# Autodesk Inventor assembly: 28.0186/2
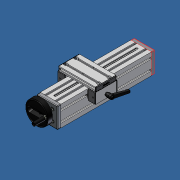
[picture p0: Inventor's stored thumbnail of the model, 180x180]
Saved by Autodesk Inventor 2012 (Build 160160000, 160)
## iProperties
Created: 2007-06
Part Number: 28.0186/2
Document SubType Name: Assembly
Designer: Andy Moles
Description: ADJUSTING UNIT VEN 90 WITH SIDE CLAMP
Author: Andy Moles
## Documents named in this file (23)
- C:\Andys Backup Data\ANDY'S INVENTOR\INVENTOR LIBRARIES\PARTS LIBRARY\READY FOR USE MODULES LG\28.0186_2 ADJUSTING UNIT VEN 90 WITH SIDE CLAMP.iam
- C:\Andys Backup Data\ANDY'S INVENTOR\INVENTOR LIBRARIES\PARTS LIBRARY\READY FOR USE MODULES LG\SUBCOMPONENTS\28.0216_1 90x90S.ipt
- C:\Andys Backup Data\ANDY'S INVENTOR\INVENTOR LIBRARIES\PARTS LIBRARY\READY FOR USE MODULES LG\SUBCOMPONENTS\50.1264 BALL BEARING 10X30X9 6200 2RS DIN 625.ipt
- C:\Andys Backup Data\ANDY'S INVENTOR\INVENTOR LIBRARIES\PARTS LIBRARY\READY FOR USE MODULES LG\SUBCOMPONENTS\28.0205 BEARING PLATE 90X90 HANDWHEEL SIDE.ipt
- C:\Andys Backup Data\ANDY'S INVENTOR\INVENTOR LIBRARIES\PARTS LIBRARY\READY FOR USE MODULES LG\SUBCOMPONENTS\28.0206 BEARING PLATE 90X90 IDLER SIDE.ipt
- C:\Andys Backup Data\ANDY'S INVENTOR\INVENTOR LIBRARIES\PARTS LIBRARY\READY FOR USE MODULES LG\SUBCOMPONENTS\28.0204 HANDWHEEL 100mm.iam
- C:\Andys Backup Data\ANDY'S INVENTOR\INVENTOR LIBRARIES\PARTS LIBRARY\READY FOR USE MODULES LG\SUBCOMPONENTS\28.0221 ACME SCREW 16X4.ipt
- C:\Andys Backup Data\ANDY'S INVENTOR\INVENTOR LIBRARIES\PARTS LIBRARY\FASTENING ELEMENTS\WASHERS\21.1326 DISC SPRING 20.ipt
- C:\Andys Backup Data\ANDY'S INVENTOR\INVENTOR LIBRARIES\PARTS LIBRARY\FASTENING ELEMENTS\SCREWS CAP\21.1204 M8X25.ipt
- C:\Andys Backup Data\ANDY'S INVENTOR\INVENTOR LIBRARIES\PARTS LIBRARY\READY FOR USE MODULES LG\SUBCOMPONENTS\28.0255 Nut slide connector 20.ipt
- C:\Andys Backup Data\ANDY'S INVENTOR\INVENTOR LIBRARIES\PARTS LIBRARY\READY FOR USE MODULES LG\SUBCOMPONENTS\28.0224_1 LWN 32X45-90 90X19-NSC.ipt
- C:\Andys Backup Data\ANDY'S INVENTOR\INVENTOR LIBRARIES\PARTS LIBRARY\READY FOR USE MODULES LG\SUBCOMPONENTS\28.0257 BRONZE NUT 16X4 NOTCHED.ipt
- C:\Andys Backup Data\ANDY'S INVENTOR\INVENTOR LIBRARIES\PARTS LIBRARY\FASTENING ELEMENTS\SCREWS CAP\21.1235 M5X16.ipt
- C:\Andys Backup Data\ANDY'S INVENTOR\INVENTOR LIBRARIES\PARTS LIBRARY\FASTENING ELEMENTS\SCREWS CAP\21.1200 M8X16.ipt
- C:\Andys Backup Data\ANDY'S INVENTOR\INVENTOR LIBRARIES\PARTS LIBRARY\READY FOR USE MODULES LG\SUBCOMPONENTS\28.0126 SLIDE 45X32.ipt
- C:\Andys Backup Data\ANDY'S INVENTOR\INVENTOR LIBRARIES\PARTS LIBRARY\READY FOR USE MODULES LG\SUBCOMPONENTS\28.0126_9 SIDE LOCK 45X32.ipt
- C:\Andys Backup Data\ANDY'S INVENTOR\INVENTOR LIBRARIES\PARTS LIBRARY\COMPONENTS LG\22.1095 SLIDE RAIL LN.iam
- C:\Andys Backup Data\ANDY'S INVENTOR\INVENTOR LIBRARIES\PARTS LIBRARY\COMPONENTS LG\22.1095_9 SLIDE RAIL LN FOR SIDE LOCK.iam
- C:\Andys Backup Data\ANDY'S INVENTOR\INVENTOR LIBRARIES\PARTS LIBRARY\END CAPS\22.1003_1 END CAP 45x32 Z Gray.iam
- C:\Andys Backup Data\ANDY'S INVENTOR\INVENTOR LIBRARIES\PARTS LIBRARY\FASTENING ELEMENTS\NUTS\21.1330 M6 SQUARE NUT.ipt
- C:\Andys Backup Data\ANDY'S INVENTOR\INVENTOR LIBRARIES\PARTS LIBRARY\END CAPS\22.1014_1 END CAP 90X19 GRAY.ipt
- C:\Andys Backup Data\ANDY'S INVENTOR\INVENTOR LIBRARIES\PARTS LIBRARY\FASTENING ELEMENTS\NUTS\21.1351 M8 SQUARE NUT.ipt
- C:\Andys Backup Data\ANDY'S INVENTOR\INVENTOR LIBRARIES\PARTS LIBRARY\COMPONENTS LG\21.1013_1 SLIDE LOCK WITH M6X50 STUD.ipt
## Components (42 placed, 22 different names)
1. 28.0216_1 90x90S:1 — Flush:1, Flush:2, Flush:3, Mate:3, Flush:10, Flush:11, Mate:10, Flush:12, Flush:13, Angle:8, Mate:26, Mate:32
2. 50.1264 10X30X9 6200 2RS DIN 625 BALL BEARING:1 — Insert:7
3. 50.1264 10X30X9 6200 2RS DIN 625 BALL BEARING:2 — Insert:6, Insert:18
4. 28.0205 BEARING PLATE 90X90 HANDWHEEL SIDE:1 — Mate:3, Insert:4, Insert:7, Flush:11, Insert:8, Insert:9, Insert:10, Insert:11, Flush:13
5. 28.0206 BEARING PLATE 90X90 IDLER SIDE:1 — Insert:6, Flush:10, Insert:12, Insert:13, Insert:14, Insert:15, Mate:10, Flush:12
6. 28.0204 HANDWHEEL 100mm:1 [sub-assembly] — Insert:4, Angle:1
7. 21.1204  M8 x 25:1 — Insert:8
8. 21.1204  M8 x 25:2 — Insert:9
9. 21.1204  M8 x 25:3 — Insert:11
10. 21.1204  M8 x 25:4 — Insert:10
11. 21.1204  M8 x 25:5 — Insert:14
12. 21.1204  M8 x 25:6 — Insert:13
13. 21.1204  M8 x 25:7 — Insert:15
14. 21.1204  M8 x 25:8 — Insert:12
15. 28.0221 ACME SCREW 16X4:1 — Insert:16, Insert:17, Angle:1, Mate:20
16. 21.1326 DISC SPRING 20:1 — Insert:16
17. 21.1326 DISC SPRING 20:2 — Insert:17, Insert:18
18. 28.0255 Nut slide connector 20:1 — Insert:19, Angle:2, Mate:27
19. 28.0224_1 LWN 32X45-90 90X19-NSC:1 — Insert:19, Angle:2, Insert:20, Insert:21, Insert:22, Insert:23, Insert:24, Mate:12, Flush:14, Angle:8, Mate:28, Flush:17, Mate:35, Angle:16, Flush:19, Flush:20, Mate:36, Flush:21, Flush:22, Insert:36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
20. 28.0257 BRONZE NUT 16X4 NOTCHED:1 — Mate:20, Mate:27
21. 21.1235  M5 x 16:1 — Insert:20
22. 21.1235  M5 x 16:2 — Insert:21
23. 21.1200 M8 x 16:1 — Insert:22, Mate:39
24. 21.1200 M8 x 16:2 — Insert:23, Mate:13, Mate:40
25. 21.1200 M8 x 16:3 — Insert:24, Mate:29, Mate:38
26. 28.0126 SLIDE 45X32:1 — Mate:12, Flush:14, Mate:13, Mate:16, Flush:16, Mate:17, Insert:31, Insert:32, Angle:11, Angle:12
27. 28.0126_9 SIDE LOCK 45X32:1 — Mate:28, Mate:29, Flush:17, Flush:18, Mate:30, Mate:31, Insert:33, Insert:34, Angle:13, Angle:14, Angle:15, Insert:37
28. 22.1095 SLIDE RAIL LN:1 [sub-assembly] — Mate:16, Flush:16, Mate:17, Mate:26
29. 22.1095_9 SLIDE RAIL LN FOR SIDE LOCK:1 [sub-assembly] — Flush:18, Mate:30, Mate:31, Mate:32, Mate:34
30. 22.1003\1 END CAP 45x32 Z Gray:1 [sub-assembly] — Insert:33, Angle:14
31. 22.1003\1 END CAP 45x32 Z Gray:2 [sub-assembly] — Insert:34, Angle:13
32. 22.1003\1 END CAP 45x32 Z Gray:3 [sub-assembly] — Insert:32, Angle:11
33. 22.1003\1 END CAP 45x32 Z Gray:4 [sub-assembly] — Insert:31, Angle:12
34. 21.1013_1 SLIDE LOCK WITH M6X50 STUD:1 — Insert:37, Angle:21, Mate:45
35. 21.1330 M6 SQUARE NUT:1 — Mate:34, Angle:15, Mate:45
36. 22.1014_1 END CAP 90X19 GRAY:1 — Mate:35, Angle:16, Flush:19, Flush:22, Angle:17, Angle:18
37. 22.1014_1 END CAP 90X19 GRAY:2 — Flush:20, Mate:36, Flush:21, Angle:19, Angle:20
38. 21.1200 M8 x 16:4 — Insert:36, Mate:37
39. 21.1351 M8 SQUARE NUT:1 — Mate:37, Mate:44, Angle:17
40. 21.1351 M8 SQUARE NUT:2 — Mate:38, Mate:43, Angle:18
41. 21.1351 M8 SQUARE NUT:3 — Mate:39, Mate:41, Angle:20
42. 21.1351 M8 SQUARE NUT:4 — Mate:40, Mate:42, Angle:19
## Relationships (81: Mate 26, Insert 26, Flush 15, Angle 14)
- Flush:1: 28.0216_1 90x90S:1
- Flush:2: 28.0216_1 90x90S:1
- Flush:3: 28.0216_1 90x90S:1
- Mate:3: 28.0216_1 90x90S:1 ↔ 28.0205 BEARING PLATE 90X90 HANDWHEEL SIDE:1
- Insert:4: 28.0205 BEARING PLATE 90X90 HANDWHEEL SIDE:1 ↔ 28.0204 HANDWHEEL 100mm:1
- Insert:6: 50.1264 10X30X9 6200 2RS DIN 625 BALL BEARING:2 ↔ 28.0206 BEARING PLATE 90X90 IDLER SIDE:1
- Insert:7: 50.1264 10X30X9 6200 2RS DIN 625 BALL BEARING:1 ↔ 28.0205 BEARING PLATE 90X90 HANDWHEEL SIDE:1
- Flush:10: 28.0216_1 90x90S:1 ↔ 28.0206 BEARING PLATE 90X90 IDLER SIDE:1
- Flush:11: 28.0216_1 90x90S:1 ↔ 28.0205 BEARING PLATE 90X90 HANDWHEEL SIDE:1
- Insert:8: 28.0205 BEARING PLATE 90X90 HANDWHEEL SIDE:1 ↔ 21.1204  M8 x 25:1
- Insert:9: 28.0205 BEARING PLATE 90X90 HANDWHEEL SIDE:1 ↔ 21.1204  M8 x 25:2
- Insert:10: 28.0205 BEARING PLATE 90X90 HANDWHEEL SIDE:1 ↔ 21.1204  M8 x 25:4
- Insert:11: 28.0205 BEARING PLATE 90X90 HANDWHEEL SIDE:1 ↔ 21.1204  M8 x 25:3
- Insert:12: 28.0206 BEARING PLATE 90X90 IDLER SIDE:1 ↔ 21.1204  M8 x 25:8
- Insert:13: 28.0206 BEARING PLATE 90X90 IDLER SIDE:1 ↔ 21.1204  M8 x 25:6
- Insert:14: 28.0206 BEARING PLATE 90X90 IDLER SIDE:1 ↔ 21.1204  M8 x 25:5
- Insert:15: 28.0206 BEARING PLATE 90X90 IDLER SIDE:1 ↔ 21.1204  M8 x 25:7
- Mate:10: 28.0216_1 90x90S:1 ↔ 28.0206 BEARING PLATE 90X90 IDLER SIDE:1
- Flush:12: 28.0216_1 90x90S:1 ↔ 28.0206 BEARING PLATE 90X90 IDLER SIDE:1
- Flush:13: 28.0216_1 90x90S:1 ↔ 28.0205 BEARING PLATE 90X90 HANDWHEEL SIDE:1
- Insert:16: 28.0221 ACME SCREW 16X4:1 ↔ 21.1326 DISC SPRING 20:1
- Insert:17: 28.0221 ACME SCREW 16X4:1 ↔ 21.1326 DISC SPRING 20:2
- Insert:18: 50.1264 10X30X9 6200 2RS DIN 625 BALL BEARING:2 ↔ 21.1326 DISC SPRING 20:2
- Angle:1: 28.0204 HANDWHEEL 100mm:1 ↔ 28.0221 ACME SCREW 16X4:1
- Insert:19: 28.0255 Nut slide connector 20:1 ↔ 28.0224_1 LWN 32X45-90 90X19-NSC:1
- Angle:2: 28.0255 Nut slide connector 20:1 ↔ 28.0224_1 LWN 32X45-90 90X19-NSC:1
- Insert:20: 28.0224_1 LWN 32X45-90 90X19-NSC:1 ↔ 21.1235  M5 x 16:1
- Insert:21: 28.0224_1 LWN 32X45-90 90X19-NSC:1 ↔ 21.1235  M5 x 16:2
- Insert:22: 28.0224_1 LWN 32X45-90 90X19-NSC:1 ↔ 21.1200 M8 x 16:1
- Insert:23: 28.0224_1 LWN 32X45-90 90X19-NSC:1 ↔ 21.1200 M8 x 16:2
- Insert:24: 28.0224_1 LWN 32X45-90 90X19-NSC:1 ↔ 21.1200 M8 x 16:3
- Mate:12: 28.0224_1 LWN 32X45-90 90X19-NSC:1 ↔ 28.0126 SLIDE 45X32:1
- Flush:14: 28.0224_1 LWN 32X45-90 90X19-NSC:1 ↔ 28.0126 SLIDE 45X32:1
- Mate:13: 21.1200 M8 x 16:2 ↔ 28.0126 SLIDE 45X32:1
- Mate:16: 28.0126 SLIDE 45X32:1 ↔ 22.1095 SLIDE RAIL LN:1
- Flush:16: 28.0126 SLIDE 45X32:1 ↔ 22.1095 SLIDE RAIL LN:1
- Mate:17: 28.0126 SLIDE 45X32:1 ↔ 22.1095 SLIDE RAIL LN:1
- Mate:20: 28.0221 ACME SCREW 16X4:1 ↔ 28.0257 BRONZE NUT 16X4 NOTCHED:1
- Angle:8: 28.0216_1 90x90S:1 ↔ 28.0224_1 LWN 32X45-90 90X19-NSC:1
- Insert:31: 28.0126 SLIDE 45X32:1 ↔ 22.1003\1 END CAP 45x32 Z Gray:4
- Insert:32: 28.0126 SLIDE 45X32:1 ↔ 22.1003\1 END CAP 45x32 Z Gray:3
- Angle:11: 28.0126 SLIDE 45X32:1 ↔ 22.1003\1 END CAP 45x32 Z Gray:3
- Angle:12: 28.0126 SLIDE 45X32:1 ↔ 22.1003\1 END CAP 45x32 Z Gray:4
- Mate:26: 28.0216_1 90x90S:1 ↔ 22.1095 SLIDE RAIL LN:1
- Mate:27: 28.0255 Nut slide connector 20:1 ↔ 28.0257 BRONZE NUT 16X4 NOTCHED:1
- Mate:28: 28.0224_1 LWN 32X45-90 90X19-NSC:1 ↔ 28.0126_9 SIDE LOCK 45X32:1
- Mate:29: 21.1200 M8 x 16:3 ↔ 28.0126_9 SIDE LOCK 45X32:1
- Flush:17: 28.0224_1 LWN 32X45-90 90X19-NSC:1 ↔ 28.0126_9 SIDE LOCK 45X32:1
- Flush:18: 28.0126_9 SIDE LOCK 45X32:1 ↔ 22.1095_9 SLIDE RAIL LN FOR SIDE LOCK:1
- Mate:30: 28.0126_9 SIDE LOCK 45X32:1 ↔ 22.1095_9 SLIDE RAIL LN FOR SIDE LOCK:1
- Mate:31: 28.0126_9 SIDE LOCK 45X32:1 ↔ 22.1095_9 SLIDE RAIL LN FOR SIDE LOCK:1
- Insert:33: 28.0126_9 SIDE LOCK 45X32:1 ↔ 22.1003\1 END CAP 45x32 Z Gray:1
- Insert:34: 28.0126_9 SIDE LOCK 45X32:1 ↔ 22.1003\1 END CAP 45x32 Z Gray:2
- Angle:13: 28.0126_9 SIDE LOCK 45X32:1 ↔ 22.1003\1 END CAP 45x32 Z Gray:2
- Angle:14: 28.0126_9 SIDE LOCK 45X32:1 ↔ 22.1003\1 END CAP 45x32 Z Gray:1
- Mate:32: 28.0216_1 90x90S:1 ↔ 22.1095_9 SLIDE RAIL LN FOR SIDE LOCK:1
- Mate:34: 22.1095_9 SLIDE RAIL LN FOR SIDE LOCK:1 ↔ 21.1330 M6 SQUARE NUT:1
- Angle:15: 28.0126_9 SIDE LOCK 45X32:1 ↔ 21.1330 M6 SQUARE NUT:1
- Mate:35: 28.0224_1 LWN 32X45-90 90X19-NSC:1 ↔ 22.1014_1 END CAP 90X19 GRAY:1
- Angle:16: 28.0224_1 LWN 32X45-90 90X19-NSC:1 ↔ 22.1014_1 END CAP 90X19 GRAY:1
- Flush:19: 28.0224_1 LWN 32X45-90 90X19-NSC:1 ↔ 22.1014_1 END CAP 90X19 GRAY:1
- Flush:20: 28.0224_1 LWN 32X45-90 90X19-NSC:1 ↔ 22.1014_1 END CAP 90X19 GRAY:2
- Mate:36: 28.0224_1 LWN 32X45-90 90X19-NSC:1 ↔ 22.1014_1 END CAP 90X19 GRAY:2
- Flush:21: 28.0224_1 LWN 32X45-90 90X19-NSC:1 ↔ 22.1014_1 END CAP 90X19 GRAY:2
- Flush:22: 28.0224_1 LWN 32X45-90 90X19-NSC:1 ↔ 22.1014_1 END CAP 90X19 GRAY:1
- Insert:36: 28.0224_1 LWN 32X45-90 90X19-NSC:1 ↔ 21.1200 M8 x 16:4
- Mate:37: 21.1200 M8 x 16:4 ↔ 21.1351 M8 SQUARE NUT:1
- Mate:38: 21.1200 M8 x 16:3 ↔ 21.1351 M8 SQUARE NUT:2
- Mate:39: 21.1200 M8 x 16:1 ↔ 21.1351 M8 SQUARE NUT:3
- Mate:40: 21.1200 M8 x 16:2 ↔ 21.1351 M8 SQUARE NUT:4
- Mate:41: 28.0224_1 LWN 32X45-90 90X19-NSC:1 ↔ 21.1351 M8 SQUARE NUT:3
- Mate:42: 28.0224_1 LWN 32X45-90 90X19-NSC:1 ↔ 21.1351 M8 SQUARE NUT:4
- Mate:43: 28.0224_1 LWN 32X45-90 90X19-NSC:1 ↔ 21.1351 M8 SQUARE NUT:2
- Mate:44: 28.0224_1 LWN 32X45-90 90X19-NSC:1 ↔ 21.1351 M8 SQUARE NUT:1
- Angle:17: 22.1014_1 END CAP 90X19 GRAY:1 ↔ 21.1351 M8 SQUARE NUT:1
- Angle:18: 22.1014_1 END CAP 90X19 GRAY:1 ↔ 21.1351 M8 SQUARE NUT:2
- Angle:19: 22.1014_1 END CAP 90X19 GRAY:2 ↔ 21.1351 M8 SQUARE NUT:4
- Angle:20: 22.1014_1 END CAP 90X19 GRAY:2 ↔ 21.1351 M8 SQUARE NUT:3
- Insert:37: 28.0126_9 SIDE LOCK 45X32:1 ↔ 21.1013_1 SLIDE LOCK WITH M6X50 STUD:1
- Angle:21: 28.0224_1 LWN 32X45-90 90X19-NSC:1 ↔ 21.1013_1 SLIDE LOCK WITH M6X50 STUD:1
- Mate:45: 21.1013_1 SLIDE LOCK WITH M6X50 STUD:1 ↔ 21.1330 M6 SQUARE NUT:1
